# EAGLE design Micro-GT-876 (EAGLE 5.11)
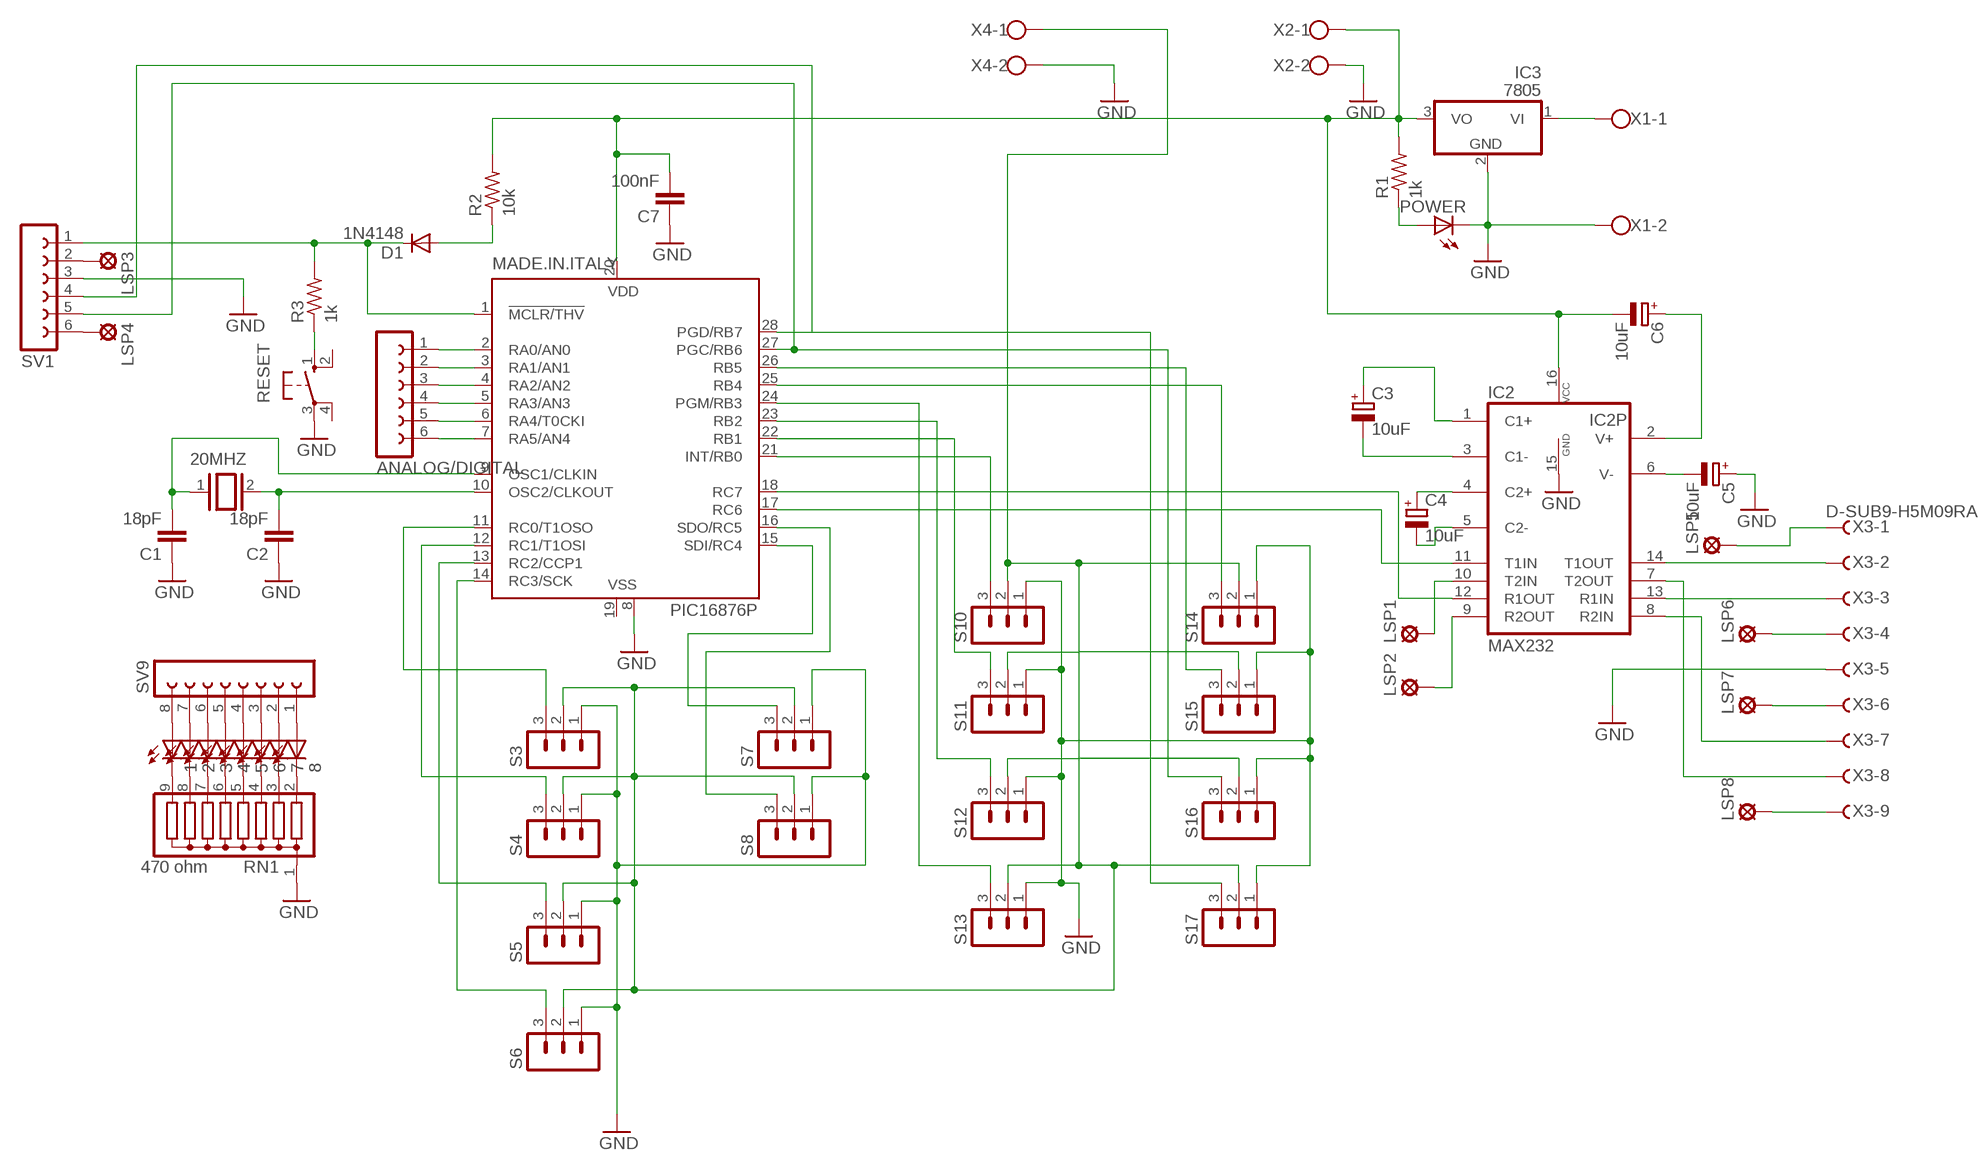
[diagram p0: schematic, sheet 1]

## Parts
1  LED3MM  [LED3MM]
2  LED3MM  [LED3MM]
3  LED3MM  [LED3MM]
4  LED3MM  [LED3MM]
5  LED3MM  [LED3MM]
6  LED3MM  [LED3MM]
7  LED3MM  [LED3MM]
8  LED3MM  [LED3MM]
20MHZ  XTAL/S  [QS]
ANALOG/DIGITAL  FE06-1  [FE06]
C1  18pF  C-EU050-024X044  [C050-024X044]
C2  18pF  C-EU050-024X044  [C050-024X044]
C3  10uF  CPOL-EUE2.5-5  [E2,5-5]
C4  10uF  CPOL-EUE2.5-5  [E2,5-5]
C5  10uF  CPOL-EUE2.5-5  [E2,5-5]
C6  10uF  CPOL-EUE2.5-5  [E2,5-5]
C7  100nF  C-EU050-024X044  [C050-024X044]
D1  1N4148  1N4148DO35-7  [DO35-7]
IC2  MAX232  [DIL16]
IC3  7805  7805TV  [TO220V]
LSP1  LSP11  [LSP11]
LSP2  LSP11  [LSP11]
LSP3  LSP11  [LSP11]
LSP4  LSP11  [LSP11]
LSP5  LSP11  [LSP11]
LSP6  LSP11  [LSP11]
LSP7  LSP11  [LSP11]
LSP8  LSP11  [LSP11]
MADE.IN.ITALY  PIC16876P  [DIL28-3]
POWER  LED3MM  [LED3MM]
R1  1k  R-US_0207/10  [0207/10]
R2  10k  R-US_0207/10  [0207/10]
R3  1k  R-US_0207/10  [0207/10]
RESET  10-XX  [B3F-10XX]
RN1  470 ohm  G08R  [SIL9]
S3  MA03-1  [MA03-1]
S4  MA03-1  [MA03-1]
S5  MA03-1  [MA03-1]
S6  MA03-1  [MA03-1]
S7  MA03-1  [MA03-1]
S8  MA03-1  [MA03-1]
S10  MA03-1  [MA03-1]
S11  MA03-1  [MA03-1]
S12  MA03-1  [MA03-1]
S13  MA03-1  [MA03-1]
S14  MA03-1  [MA03-1]
S15  MA03-1  [MA03-1]
S16  MA03-1  [MA03-1]
S17  MA03-1  [MA03-1]
SV1  FE06-1  [FE06]
SV9  FE08-1  [FE08]
X1  W237-02P  [W237-132]
X2  W237-02P  [W237-132]
X3  D-SUB9-H5M09RA  [H5M09RA]
X4  W237-02P  [W237-132]

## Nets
GND: C1.1 C2.1 C5.+ C7.1 IC2.15(GND) IC3.2(GND) MADE.IN.ITALY.8(VSS) POWER.K(C) RESET.3(P) RN1.1 S3.1 S4.1 S5.1 S6.1 S7.1 S8.1 S10.1 S11.1 S12.1 S13.1 S14.1 S15.1 S16.1 S17.1 SV1.3 X1.2 X2.2 X3.5 X4.2
N$1: ANALOG/DIGITAL.1 MADE.IN.ITALY.2(RA0/AN0)
N$2: ANALOG/DIGITAL.2 MADE.IN.ITALY.3(RA1/AN1)
N$3: ANALOG/DIGITAL.3 MADE.IN.ITALY.4(RA2/AN2)
N$4: ANALOG/DIGITAL.4 MADE.IN.ITALY.5(RA3/AN3)
N$5: ANALOG/DIGITAL.5 MADE.IN.ITALY.6(RA4/T0CKI)
N$6: ANALOG/DIGITAL.6 MADE.IN.ITALY.7(RA5/AN4)
N$7: MADE.IN.ITALY.21(INT/RB0) S10.3
N$8: MADE.IN.ITALY.22(RB1) S11.3
N$9: MADE.IN.ITALY.23(RB2) S12.3
N$10: MADE.IN.ITALY.24(PGM/RB3) S13.3
N$11: MADE.IN.ITALY.25(RB4) S14.3
N$12: MADE.IN.ITALY.26(RB5) S15.3
N$17: IC2.11(T1IN) MADE.IN.ITALY.17(RC6)
N$18: IC2.12(R1OUT) MADE.IN.ITALY.18(RC7)
N$19: D1.A R2.1
N$20: POWER.A R1.1
N$21: C6.- C7.2 IC2.16(VCC) IC3.3(VO) MADE.IN.ITALY.20(VDD) R1.2 R2.2 X2.1
N$22: R3.1 RESET.1(S)
N$23: D1.C MADE.IN.ITALY.1(!MCLR/THV) R3.2 SV1.1
N$24: IC3.1(VI) X1.1
N$25: IC2.10(T2IN) LSP1.MP
N$26: 20MHZ.1 C1.2 MADE.IN.ITALY.9(OSC1/CLKIN)
N$27: 20MHZ.2 C2.2 MADE.IN.ITALY.10(OSC2/CLKOUT)
N$28: IC2.9(R2OUT) LSP2.MP
N$29: LSP3.MP SV1.2
N$30: LSP4.MP SV1.6
N$31: C3.- IC2.3(C1-)
N$32: C3.+ IC2.1(C1+)
N$33: C4.+ IC2.4(C2+)
N$34: C4.- IC2.5(C2-)
N$35: C5.- IC2.6(V-)
N$36: S3.2 S4.2 S5.2 S6.2 S7.2 S8.2 S10.2 S11.2 S12.2 S13.2 S14.2 S15.2 S16.2 S17.2 X4.1
N$37: C6.+ IC2.2(V+)
N$38: MADE.IN.ITALY.11(RC0/T1OSO) S3.3
N$39: MADE.IN.ITALY.12(RC1/T1OSI) S4.3
N$40: MADE.IN.ITALY.13(RC2/CCP1) S5.3
N$41: IC2.14(T1OUT) X3.2
N$42: IC2.7(T2OUT) X3.8
N$43: IC2.8(R2IN) X3.7
N$44: IC2.13(R1IN) X3.3
N$45: MADE.IN.ITALY.27(PGC/RB6) S16.3 SV1.5
N$46: MADE.IN.ITALY.28(PGD/RB7) S17.3 SV1.4
N$47: 1.K(C) RN1.9
N$48: 1.A SV9.8
N$49: LSP5.MP X3.1
N$50: LSP6.MP X3.4
N$51: LSP7.MP X3.6
N$52: LSP8.MP X3.9
N$53: 2.K(C) RN1.8
N$54: 2.A SV9.7
N$55: 3.K(C) RN1.7
N$56: 3.A SV9.6
N$57: 4.K(C) RN1.6
N$58: 4.A SV9.5
N$59: 5.K(C) RN1.5
N$60: 5.A SV9.4
N$61: 6.K(C) RN1.4
N$62: 6.A SV9.3
N$63: 7.K(C) RN1.3
N$64: 7.A SV9.2
N$65: 8.K(C) RN1.2
N$66: 8.A SV9.1
N$67: MADE.IN.ITALY.14(RC3/SCK) S6.3
N$69: MADE.IN.ITALY.16(SDO/RC5) S8.3
N$72: MADE.IN.ITALY.15(SDI/RC4) S7.3
Unconnected: RESET.2(S1) RESET.4(P1)

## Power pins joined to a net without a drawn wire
VSS: MADE.IN.ITALY.19(VSS)

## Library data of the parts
1-8 POWER = led:LED: LED
20MHZ = special:XTAL/S: CRYSTAL
ANALOG/DIGITAL SV1 = con-lsta:FE06-1: FEMALE HEADER
C1 C2 C7 = resistor:C-EU: CAPACITOR, European symbol
C3-C6 = resistor:CPOL-EU: POLARIZED CAPACITOR, European symbol
D1 = diode:1N4148: DIODE
IC2 = maxim:MAX232: RS232 TRANSEIVER
IC3 = linear:78*: Positive VOLTAGE REGULATOR Source: http://cache.national.com/ds/LM/LM78L05.pdf http://www.fairchildsemi.com/ds/LM/LM7805.pdf
LSP1-LSP8 = solpad:LSP11: SOLDER PAD
MADE.IN.ITALY = microchip:PIC16*876: MICROCONTROLLER flash type
R1-R3 = rcl:R-US_: RESISTOR, American symbol
RESET = switch-omron:10-XX: OMRON SWITCH
RN1 = resistor-sil:G08R: SIL RESISTOR
S3-S8 S10-S17 = microGTmini:MA03-1: PIN HEADER; OC_FARNELL: unknown; OC_NEWARK: unknown
SV9 = con-lsta:FE08-1: FEMALE HEADER
X1 X2 X4 = con-wago-508:W237-02P: WAGO SREW CLAMP
X3 = con-thomas-betts:D-SUB9-: D-Subminiatur Connector Source: Electronioc Interconnects European Edition 1998

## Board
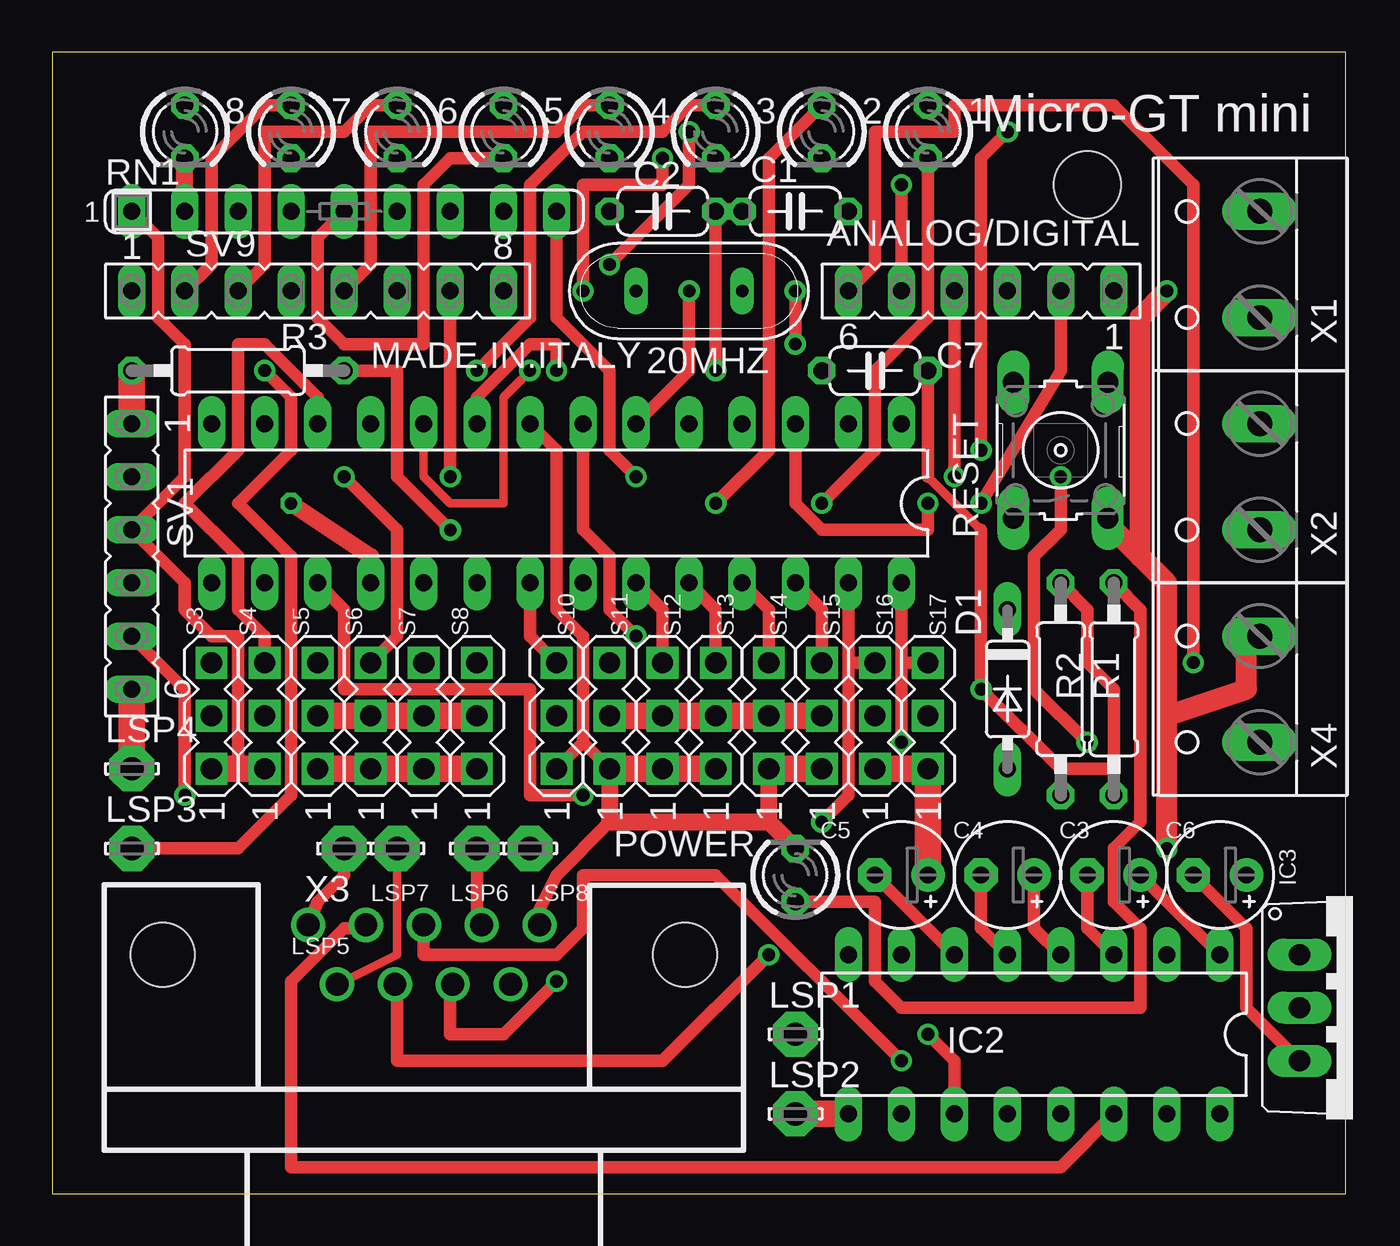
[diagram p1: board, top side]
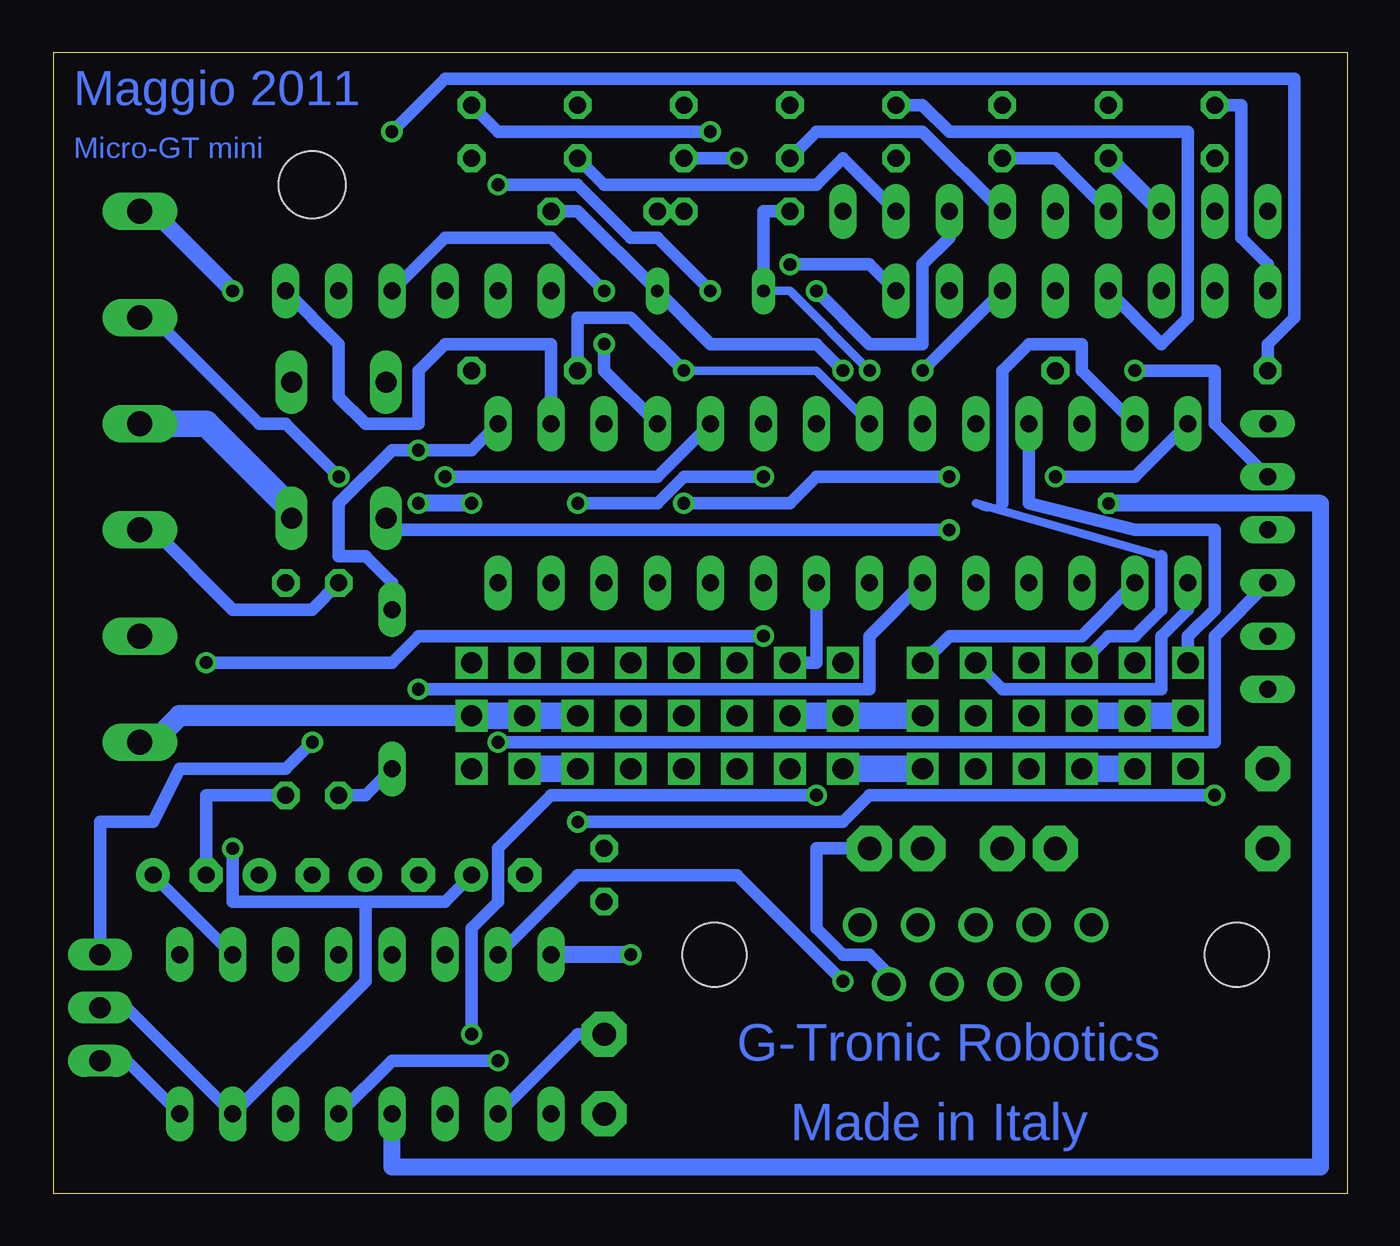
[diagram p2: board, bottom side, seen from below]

Size 61.9 x 54.6 mm. Coordinates in mm from the lower left corner, seen from the top.
Outline: 0,0 61.9,0 61.9,54.6 0,54.6 0,0
Copper layers (1*16): Top 0.035mm / dielectric 1.5mm / Bottom 0.035mm
Design rules "default": minimum track width 10mil, minimum drill 24mil, track to track 8mil, track to pad 8mil, pad to pad 8mil, via to via 8mil, smd to smd 8mil, copper to edge 40mil, drill to drill 8mil, minimum pad ring 10mil, minimum via ring 8mil, stop-mask expansion 4mil, vias tented up to drill 0mil, thermal gap 10mil
Holes 3.2 mm at 49.53,48.26

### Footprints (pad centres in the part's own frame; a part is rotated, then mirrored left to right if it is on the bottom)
LED3MM = drill 0.813 octagon: A -1.27,0; K 1.27,0
QS = drill 0.61 long: 1 -2.54,0; 2 2.54,0
FE06 = drill 0.813 long: 1 -6.35,0; 2 -3.81,0; 3 -1.27,0; 4 1.27,0; 5 3.81,0; 6 6.35,0
C050-024X044 = drill 0.813 octagon: 1 -2.54,0; 2 2.54,0
E2,5-5 = drill 0.813 pad 1.6 round: + -1.27,0 | drill 0.813 pad 1.6 octagon: - 1.27,0
DO35-7 = drill 0.813 long: A 3.81,0; C -3.81,0
DIL16 = drill 0.813 long: 1 -8.89,-3.81; 2 -6.35,-3.81; 3 -3.81,-3.81; 4 -1.27,-3.81; 5 1.27,-3.81; 6 3.81,-3.81; 7 6.35,-3.81; 8 8.89,-3.81; 9 8.89,3.81; 10 6.35,3.81; 11 3.81,3.81; 12 1.27,3.81; 13 -1.27,3.81; 14 -3.81,3.81; 15 -6.35,3.81; 16 -8.89,3.81
TO220V = drill 1.016 long: 1 -2.54,-2.54; 2 0,-2.54; 3 2.54,-2.54
LSP11 = drill 1.118 pad 2.159 octagon: MP 0,0
DIL28-3 = drill 0.813 long: 1 -16.51,-3.81; 2 -13.97,-3.81; 3 -11.43,-3.81; 4 -8.89,-3.81; 5 -6.35,-3.81; 6 -3.81,-3.81; 7 -1.27,-3.81; 8 1.27,-3.81; 9 3.81,-3.81; 10 6.35,-3.81; 11 8.89,-3.81; 12 11.43,-3.81; 13 13.97,-3.81; 14 16.51,-3.81; 15 16.51,3.81; 16 13.97,3.81; 17 11.43,3.81; 18 8.89,3.81; 19 6.35,3.81; 20 3.81,3.81; 21 1.27,3.81; 22 -1.27,3.81; 23 -3.81,3.81; 24 -6.35,3.81; 25 -8.89,3.81; 26 -11.43,3.81; 27 -13.97,3.81; 28 -16.51,3.81
0207/10 = drill 0.813 octagon: 1 -5.08,0; 2 5.08,0
B3F-10XX = drill 1.016 long: 1 -3.251,2.261; 2 3.251,2.261; 3 -3.251,-2.261; 4 3.251,-2.261
SIL9 = drill 0.813 long: 1 -10.16,0; 2 -7.62,0; 3 -5.08,0; 4 -2.54,0; 5 0,0; 6 2.54,0; 7 5.08,0; 8 7.62,0; 9 10.16,0
MA03-1 = drill 1.016 square: 1 -2.54,0; 2 0,0; 3 2.54,0
FE08 = drill 0.813 long: 1 -8.89,0; 2 -6.35,0; 3 -3.81,0; 4 -1.27,0; 5 1.27,0; 6 3.81,0; 7 6.35,0; 8 8.89,0
W237-132 = drill 1.194 long: 1 -2.54,-0.635; 2 2.54,-0.635
H5M09RA = drill 1.092 round: 1 -5.537,1.422; 2 -2.769,1.422; 3 0,1.422; 4 2.769,1.422; 5 5.537,1.422; 6 -4.153,-1.422; 7 -1.384,-1.422; 8 1.384,-1.422; 9 4.153,-1.422 | hole 3.048: -12.497,0; 12.497,0

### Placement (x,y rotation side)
1  41.91,50.8 270 top
2  36.83,50.8 270 top
3  31.75,50.8 270 top
4  26.67,50.8 270 top
5  21.59,50.8 270 top
6  16.51,50.8 270 top
7  11.43,50.8 270 top
8  6.35,50.8 270 top
20MHZ  30.48,43.18 180 top
ANALOG/DIGITAL  44.45,43.18 180 top
C1  35.56,46.99 0 top
C2  29.21,46.99 180 top
C3  50.8,15.24 180 top
C4  45.72,15.24 180 top
C5  40.64,15.24 180 top
C6  55.88,15.24 180 top
C7  39.37,39.37 0 top
D1  45.72,24.13 270 top
IC2  46.99,7.62 180 top
IC3  62.23,8.89 270 top
LSP1  35.56,7.62 0 top
LSP2  35.56,3.81 0 top
LSP3  3.81,16.51 0 top
LSP4  3.81,20.32 0 top
LSP5  13.97,16.51 0 top
LSP6  20.32,16.51 0 top
LSP7  16.51,16.51 0 top
LSP8  22.86,16.51 0 top
MADE.IN.ITALY  24.13,33.02 180 top
POWER  35.56,15.24 90 top
R1  50.8,24.13 270 top
R2  48.26,24.13 90 top
R3  8.89,39.37 180 top
RESET  48.26,35.56 90 top
RN1  13.97,46.99 0 top
S3  7.62,22.86 90 top
S4  10.16,22.86 90 top
S5  12.7,22.86 90 top
S6  15.24,22.86 90 top
S7  17.78,22.86 90 top
S8  20.32,22.86 90 top
S10  24.13,22.86 90 top
S11  26.67,22.86 90 top
S12  29.21,22.86 90 top
S13  31.75,22.86 90 top
S14  34.29,22.86 90 top
S15  36.83,22.86 90 top
S16  39.37,22.86 90 top
S17  41.91,22.86 90 top
SV1  3.81,30.48 270 top
SV9  12.7,43.18 0 top
X1  57.15,44.45 90 top
X2  57.15,34.29 90 top
X3  17.78,11.43 0 top
X4  57.15,24.13 90 top

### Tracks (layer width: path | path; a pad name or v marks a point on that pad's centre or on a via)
GND  (via drill 0.61)
  Top 0.254: 50.8,31.75 RESET.3 | 57.15,26.67 X4.2
  Top 0.61: RN1.1 5.08,45.72 5.08,41.91 6.35,40.64 6.35,34.29 SV1.3 6.35,29.21 6.35,27.94 7.62,26.67 8.89,26.67 8.89,20.32 | MADE.IN.ITALY.8 24.13,35.56 24.13,27.94 25.4,26.67 25.4,21.59 | S10.1 25.4,21.59 | 25.4,21.59 S11.1 | v31.75,39.37 C2.1 | 26.67,17.78 24.13,15.24 22.86,12.7 X3.5
  Top 0.813: C2.1 C1.1 | S11.1 26.67,17.78 34.29,17.78 | 34.29,17.78 POWER.K | 34.29,17.78 S14.1
  Top 1.016: 53.34,22.86 53.34,29.21 52.07,30.48 | 52.07,30.48 50.8,31.75 | v53.34,43.18 52.07,41.91 52.07,30.48 | 57.15,26.67 57.15,24.13 53.34,22.86 | v53.34,16.51 53.34,22.86
  Top 1.27: S4.1 8.89,20.32 S3.1 | S5.1 S6.1 S7.1 S8.1 | S11.1 S12.1 S13.1 | S14.1 S15.1 | S16.1 S17.1 C5.+
  Bottom 0.254: RESET.3 50.8,33.02 | 57.15,46.99 X1.2
  Bottom 0.406: v31.75,39.37 25.4,39.37 MADE.IN.ITALY.8
  Bottom 0.61: C7.1 36.83,41.91 34.29,41.91 v31.75,39.37 | IC3.2 58.42,8.89 IC2.15 46.99,10.16 46.99,13.97 | 46.99,13.97 43.18,13.97 C5.+ | v53.34,16.51 53.34,13.97 46.99,13.97
  Bottom 0.813: v53.34,43.18 57.15,46.99
  Bottom 1.27: S4.1 S5.1 | S8.1 S10.1 | 50.8,33.02 54.61,36.83 X2.2 | S15.1 S16.1
N$1
  Bottom 0.61: MADE.IN.ITALY.2 38.1,40.64 43.18,40.64 44.45,39.37 44.45,36.83 46.99,36.83 48.26,38.1 48.26,40.64 ANALOG/DIGITAL.1
N$2  (via drill 0.61)
  Top 0.61: MADE.IN.ITALY.3 35.56,33.02 36.83,31.75 41.91,31.75 v41.91,33.02 | v44.45,33.02 48.26,39.37 ANALOG/DIGITAL.2
  Bottom 0.813: v41.91,33.02 v44.45,33.02
N$3  (via drill 0.61)
  Top 0.61: v35.56,40.64 v35.56,43.18
  Bottom 0.61: MADE.IN.ITALY.4 35.56,39.37 v35.56,40.64 | v35.56,43.18 38.1,45.72 43.18,45.72 ANALOG/DIGITAL.3
N$4  (via drill 0.61)
  Top 0.61: v43.18,34.29 ANALOG/DIGITAL.4
  Bottom 0.61: MADE.IN.ITALY.5 33.02,34.29 v43.18,34.29
N$5  (via drill 0.61)
  Top 0.61: MADE.IN.ITALY.6 30.48,39.37 v30.48,43.18 | v40.64,48.26 ANALOG/DIGITAL.5
  Bottom 0.61: v30.48,43.18 33.02,45.72 34.29,45.72 36.83,48.26 v40.64,48.26
N$6  (via drill 0.61)
  Top 0.61: MADE.IN.ITALY.7 25.4,31.75 26.67,30.48 26.67,27.94 v27.94,26.67 | v54.61,25.4 54.61,48.26 50.8,52.07 43.18,52.07 43.18,50.8 39.37,50.8 39.37,44.45 ANALOG/DIGITAL.6
  Bottom 0.61: v27.94,26.67 44.45,26.67 45.72,25.4 v54.61,25.4
N$7
  Top 0.61: MADE.IN.ITALY.21 22.86,26.67 S10.3
N$8
  Bottom 0.61: MADE.IN.ITALY.22 25.4,25.4 S11.3
N$9
  Top 0.61: MADE.IN.ITALY.23 29.21,27.94 S12.3
N$10
  Top 0.61: MADE.IN.ITALY.24 31.75,27.94 S13.3
N$11
  Top 0.61: MADE.IN.ITALY.25 34.29,27.94 S14.3
N$12
  Top 0.61: MADE.IN.ITALY.26 36.83,27.94 S15.3
N$17  (via drill 0.61)
  Top 0.61: MADE.IN.ITALY.17 13.97,27.94 13.97,24.13 22.86,24.13 22.86,19.05 v25.4,19.05 | v41.91,7.62 43.18,6.35 IC2.11
  Bottom 0.61: v25.4,19.05 38.1,19.05 40.64,16.51 40.64,13.97 41.91,12.7 v41.91,7.62
N$18  (via drill 0.6)
  Top 0.813: MADE.IN.ITALY.18 15.24,30.48 v11.43,33.02
  Bottom 0.813: IC2.12 45.72,1.27 1.27,1.27 1.27,33.02 v11.43,33.02
N$19
  Bottom 0.61: D1.A 46.99,19.05 R2.1
N$20
  Top 0.61: POWER.A 39.37,13.97 39.37,10.16 40.64,8.89 52.07,8.89 52.07,12.7 50.8,13.97 50.8,16.51 52.07,17.78 52.07,27.94 R1.1
N$21  (via drill 0.61)
  Top 0.406: 44.45,31.75 41.91,34.29
  Top 0.61: 50.8,20.32 48.26,20.32 v44.45,24.13 44.45,31.75 | 50.8,20.32 R1.2 | R2.2 49.53,27.94 49.53,25.4 50.8,24.13 50.8,20.32 | 41.91,34.29 C7.2 | IC3.3 57.15,8.89 57.15,12.7 C6.-
  Bottom 0.254: 57.15,31.75 X2.1
  Bottom 0.61: IC2.16 58.42,6.35 IC3.3 | MADE.IN.ITALY.20 22.86,26.67 22.86,24.13 v44.45,24.13 | C6.- 54.61,19.05 R1.2 | 57.15,31.75 53.34,27.94 49.53,27.94 R2.2
N$22  (via drill 0.61)
  Top 0.61: R3.1 16.51,39.37 16.51,34.29 v19.05,31.75
  Bottom 0.254: 45.72,31.75 RESET.1
  Bottom 0.61: v19.05,31.75 45.72,31.75
N$23  (via drill 0.61)
  Top 0.61: v45.72,50.8 44.45,49.53 v44.45,35.56
  Top 1.27: SV1.1 R3.2
  Bottom 0.61: MADE.IN.ITALY.1 41.91,35.56 v44.45,35.56 45.72,35.56 48.26,33.02 48.26,30.48 46.99,30.48 45.72,29.21 D1.C | R3.2 3.81,40.64 2.54,41.91 2.54,53.34 43.18,53.34 v45.72,50.8
N$24  (via drill 0.61)
  Top 0.61: v49.53,21.59 46.99,24.13 46.99,30.48 48.26,31.75 v48.26,34.29
  Bottom 0.61: IC3.1 59.69,17.78 57.15,17.78 55.88,20.32 50.8,20.32 v49.53,21.59 | v48.26,34.29 50.8,36.83 52.07,36.83 57.15,41.91 X1.1
N$25
  Bottom 0.61: IC2.10 36.83,7.62 LSP1.MP
N$26  (via drill 0.61)
  Top 0.254: MADE.IN.ITALY.9 20.32,38.1
  Top 0.61: 20.32,38.1 22.86,40.64 24.13,40.64 v24.13,39.37
  Bottom 0.61: C1.2 36.83,46.99 20MHZ.1 30.48,40.64 25.4,40.64 v24.13,39.37
N$27  (via drill 0.61)
  Top 0.406: MADE.IN.ITALY.10 17.78,34.29 19.05,33.02 21.59,33.02 21.59,38.1 v22.86,39.37
  Bottom 0.406: v22.86,39.37 26.67,43.18 20MHZ.2
  Bottom 0.61: 20MHZ.2 27.94,46.99 C2.2
N$28
  Top 1.27: LSP2.MP IC2.9
N$29  (via drill 0.61)
  Top 0.61: v10.16,39.37 11.43,38.1 11.43,35.56 8.89,33.02 11.43,30.48 11.43,19.05 8.89,16.51 LSP3.MP
  Bottom 0.61: SV1.2 6.35,36.83 6.35,39.37 v10.16,39.37
N$30
  Top 1.27: LSP4.MP SV1.6
N$31
  Top 0.61: IC2.3 49.53,12.7 C3.-
N$32
  Top 0.61: C3.+ IC2.1
N$33
  Top 0.61: IC2.4 46.99,12.7 C4.+
N$34
  Top 0.61: IC2.5 44.45,12.7 C4.-
N$35
  Top 0.61: C5.- IC2.6
N$36
  Top 1.27: S5.2 S6.2 S7.2 S8.2 | S11.2 S12.2 S13.2 S14.2 S15.2
  Bottom 0.254: 57.15,21.59 X4.1
  Bottom 1.016: 57.15,21.59 55.88,22.86 S17.2
  Bottom 1.27: S3.2 S4.2 S5.2 | S11.2 S10.2 S8.2 | S15.2 S16.2 S17.2
N$37
  Bottom 0.61: IC2.2 C6.+
N$38
  Bottom 0.61: MADE.IN.ITALY.11 15.24,33.02 10.16,31.75 6.35,31.75 6.35,27.94 7.62,26.67 S3.3
N$39
  Top 0.61: MADE.IN.ITALY.12 12.7,38.1 10.16,40.64 8.89,40.64 8.89,35.56 6.35,33.02 8.89,30.48 8.89,27.94 10.16,26.67 S4.3
N$40
  Bottom 0.254: 17.78,33.02 arc-90 16.51,33.02
  Bottom 0.406: 8.89,30.48 17.78,33.02
  Bottom 0.61: MADE.IN.ITALY.13 12.7,39.37 12.7,40.64 15.24,40.64 16.51,39.37 16.51,33.02 | 8.89,30.48 8.89,27.94 10.16,26.67 11.43,26.67 S5.3
N$41
  Top 0.254: 15.24,12.7 X3.2
  Top 0.61: IC2.14 48.26,1.27 11.43,1.27 11.43,10.16 13.97,12.7 15.24,12.7
N$42  (via drill 0.61)
  Top 0.254: X3.8 19.05,10.16
  Top 0.61: v24.13,10.16 21.59,7.62 19.05,7.62 19.05,10.16
  Bottom 0.61: IC2.7 36.83,15.24 29.21,15.24 v24.13,10.16
N$43  (via drill 0.61)
  Top 0.254: 16.51,10.16 X3.7
  Top 0.61: v34.29,11.43 29.21,6.35 16.51,6.35 16.51,10.16
  Bottom 0.813: v34.29,11.43 IC2.8
N$44  (via drill 0.61)
  Top 0.61: v40.64,6.35 31.75,15.24 25.4,15.24 25.4,12.7 24.13,11.43 17.78,11.43 X3.3
  Bottom 0.61: IC2.13 45.72,6.35 v40.64,6.35
N$45  (via drill 0.61)
  Top 0.61: SV1.5 6.35,24.13 v6.35,19.05 | v36.83,17.78 38.1,19.05 38.1,25.4 | 38.1,25.4 MADE.IN.ITALY.27 | 38.1,25.4 S16.3
  Bottom 0.61: v6.35,19.05 22.86,19.05 24.13,17.78 v36.83,17.78
N$46  (via drill 0.61)
  Top 0.61: 40.64,25.4 MADE.IN.ITALY.28 | v40.64,21.59 40.64,25.4 | 40.64,25.4 S17.3
  Bottom 0.61: SV1.4 6.35,26.67 6.35,21.59 v40.64,21.59
N$47  (via drill 0.61)
  Top 0.61: RN1.9 24.13,41.91 26.67,39.37 26.67,35.56 v27.94,34.29 | v36.83,33.02 39.37,35.56 39.37,39.37 41.91,41.91 1.K
  Bottom 0.61: v27.94,34.29 31.75,34.29 33.02,33.02 v36.83,33.02
N$48  (via drill 0.61)
  Top 0.61: v26.67,44.45 30.48,48.26 v30.48,50.8
  Bottom 0.61: SV9.8 22.86,44.45 v26.67,44.45 | v30.48,50.8 40.64,50.8 1.A
N$49
  Top 0.61: LSP5.MP 13.97,15.24 12.7,13.97 X3.1
N$50
  Top 0.254: X3.4 20.32,12.7
  Top 0.61: 20.32,12.7 LSP6.MP
N$51
  Top 0.254: X3.6 13.97,10.16
  Top 0.406: 13.97,10.16 16.51,11.43 LSP7.MP
N$52
  Bottom 0.254: X3.9 21.59,10.16
  Bottom 0.61: 21.59,10.16 22.86,11.43 24.13,11.43 25.4,12.7 25.4,16.51 LSP8.MP
N$53
  Bottom 0.61: RN1.8 24.13,49.53 25.4,48.26 35.56,48.26 2.K
N$54  (via drill 0.61)
  Top 0.61: v19.05,34.29 SV9.7 | v31.75,33.02 34.29,35.56 34.29,49.53 2.A
  Bottom 0.61: v19.05,34.29 25.4,34.29 26.67,33.02 v31.75,33.02
N$55  (via drill 0.61)
  Top 0.61: v25.4,43.18 25.4,48.26 29.21,48.26 v29.21,49.53
  Bottom 0.61: RN1.7 19.05,45.72 20.32,44.45 20.32,40.64 22.86,40.64 v25.4,43.18 | v29.21,49.53 3.K
N$56  (via drill 0.61)
  Top 0.61: v20.32,39.37 22.86,41.91 22.86,48.26 25.4,50.8 29.21,50.8 30.48,52.07 3.A
  Bottom 0.61: SV9.6 v20.32,39.37
N$57
  Bottom 0.61: RN1.6 20.32,50.8 25.4,50.8 4.K
N$58
  Top 0.61: SV9.5 15.24,44.45 15.24,50.8 24.13,50.8 25.4,52.07 4.A
N$59
  Top 0.61: RN1.5 12.7,45.72 12.7,41.91 13.97,40.64 17.78,40.64 17.78,48.26 19.05,49.53 5.K
N$60
  Bottom 0.61: SV9.4 8.89,40.64 7.62,41.91 7.62,50.8 19.05,50.8 20.32,52.07 5.A
N$61
  Bottom 0.61: RN1.4 13.97,49.53 6.K
N$62
  Top 0.61: SV9.3 10.16,44.45 10.16,50.8 13.97,50.8 15.24,52.07 6.A
N$63
  Bottom 0.813: RN1.3 7.K
N$64
  Top 0.61: SV9.2 7.62,44.45 7.62,49.53 10.16,52.07 7.A
N$65
  Top 0.813: RN1.2 8.K
N$66
  Bottom 0.254: SV9.1 3.81,44.45
  Bottom 0.61: 3.81,44.45 5.08,45.72 5.08,52.07 8.A
N$67  (via drill 0.61)
  Top 0.61: v13.97,34.29 16.51,31.75 16.51,26.67 S6.3
  Bottom 0.61: MADE.IN.ITALY.14 10.16,34.29 v13.97,34.29
N$69
  Bottom 0.61: MADE.IN.ITALY.16 12.7,26.67 19.05,26.67 S8.3
N$72
  Bottom 0.61: MADE.IN.ITALY.15 7.62,27.94 8.89,26.67 8.89,24.13 16.51,24.13 S7.3

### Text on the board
Bottom: Maggio 2011 | Micro-GT mini | G-Tronic Robotics | Made in Italy
tNames: Micro-GT mini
